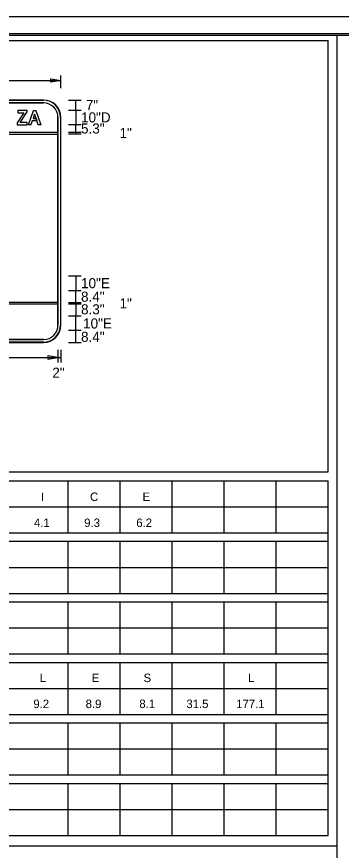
# Model space of a CAD drawing. Extents: x 17890628 to 17890817, y 17897493 to 17897992.
# Drawn here: x 17890717.8 to 17890736.57, y 17897548.59 to 17897596.75 of the extents above; entities that cross this region are included whole.
import ezdxf

# ---------------------------------------------------------------- set-up
doc = ezdxf.new("R2010")
doc.units = 0
for name, color, linetype in [('GSBWFill', 7, 'Continuous'), ('GSColorFill', 7, 'Continuous'), ('GSDims', 7, 'Continuous'), ('GSOutline', 7, 'Continuous'), ('GSSign', 7, 'Continuous'), ('PlotBorder_dp', 7, 'Continuous'), ('SheetBorder_dp', 7, 'Continuous'), ('SheetLinesMisc2_dp', 7, 'Continuous')]:
    doc.layers.add(name, color=color, linetype=linetype)

msp = doc.modelspace()

# ---------------------------------------------------------------- linework, layer by layer
at = {"layer": 'GSBWFill'}
for p, q in [((17890719.353, 17897591.936), (17890701.353, 17897591.936)), ((17890701.353, 17897591.769), (17890719.353, 17897591.769)), ((17890720.187, 17897590.936), (17890720.187, 17897578.936)), ((17890720.353, 17897578.936), (17890720.353, 17897590.936)), ((17890720.187, 17897590.054), (17890700.52, 17897590.054)), ((17890700.52, 17897589.97), (17890720.187, 17897589.97)), ((17890720.187, 17897589.97), (17890720.187, 17897590.054)), ((17890720.187, 17897580.24), (17890700.52, 17897580.24)), ((17890700.52, 17897580.156), (17890720.187, 17897580.156)), ((17890720.187, 17897580.156), (17890720.187, 17897580.24)), ((17890719.353, 17897578.102), (17890701.355, 17897578.102)), ((17890701.355, 17897577.936), (17890719.353, 17897577.936))]:
    msp.add_line(p, q, dxfattribs=at)
for points in [[(17890718.211, 17897591.199), (17890717.837, 17897590.611), (17890717.837, 17897590.499), (17890718.403, 17897590.499), (17890718.403, 17897590.632), (17890718.008, 17897590.632), (17890718.403, 17897591.253), (17890718.403, 17897591.332), (17890717.87, 17897591.332), (17890717.87, 17897591.199)], [(17890718.48, 17897590.499), (17890718.763, 17897591.332), (17890718.905, 17897591.332), (17890719.188, 17897590.499), (17890719.048, 17897590.499), (17890718.834, 17897591.126), (17890718.744, 17897590.861), (17890718.924, 17897590.861), (17890718.97, 17897590.728), (17890718.699, 17897590.728), (17890718.621, 17897590.499)]]:
    msp.add_lwpolyline(points, close=True, dxfattribs=at)
for centre, radius, start, end in [((17890719.353, 17897590.936), 1, 0, 90), ((17890719.353, 17897590.936), 0.833, 0, 90), ((17890719.353, 17897578.936), 1, 270, 0), ((17890719.353, 17897578.936), 0.833, 270, 0)]:
    msp.add_arc(centre, radius, start, end, dxfattribs=at)
at = {"layer": 'GSColorFill'}
for p, q in [((17890719.353, 17897591.936), (17890701.353, 17897591.936)), ((17890719.353, 17897591.936), (17890701.353, 17897591.936)), ((17890719.353, 17897591.936), (17890701.353, 17897591.936)), ((17890701.353, 17897591.919), (17890719.353, 17897591.919)), ((17890701.353, 17897591.769), (17890719.353, 17897591.769)), ((17890720.187, 17897590.936), (17890720.187, 17897578.936)), ((17890720.337, 17897590.936), (17890720.337, 17897578.936)), ((17890720.353, 17897578.936), (17890720.353, 17897590.936)), ((17890720.353, 17897578.936), (17890720.353, 17897590.936)), ((17890720.353, 17897578.936), (17890720.353, 17897590.936)), ((17890720.187, 17897590.054), (17890700.52, 17897590.054)), ((17890700.52, 17897589.97), (17890720.187, 17897589.97)), ((17890720.187, 17897589.97), (17890720.187, 17897590.054)), ((17890720.187, 17897580.24), (17890700.52, 17897580.24)), ((17890700.52, 17897580.156), (17890720.187, 17897580.156)), ((17890720.187, 17897580.156), (17890720.187, 17897580.24)), ((17890719.353, 17897578.102), (17890701.355, 17897578.102)), ((17890701.353, 17897577.936), (17890719.353, 17897577.936)), ((17890719.353, 17897577.952), (17890701.354, 17897577.952)), ((17890701.354, 17897577.936), (17890719.353, 17897577.936)), ((17890701.355, 17897577.936), (17890719.353, 17897577.936))]:
    msp.add_line(p, q, dxfattribs=at)
for points in [[(17890718.211, 17897591.199), (17890717.837, 17897590.611), (17890717.837, 17897590.499), (17890718.403, 17897590.499), (17890718.403, 17897590.632), (17890718.008, 17897590.632), (17890718.403, 17897591.253), (17890718.403, 17897591.332), (17890717.87, 17897591.332), (17890717.87, 17897591.199)], [(17890718.48, 17897590.499), (17890718.763, 17897591.332), (17890718.905, 17897591.332), (17890719.188, 17897590.499), (17890719.048, 17897590.499), (17890718.834, 17897591.126), (17890718.744, 17897590.861), (17890718.924, 17897590.861), (17890718.97, 17897590.728), (17890718.699, 17897590.728), (17890718.621, 17897590.499)]]:
    msp.add_lwpolyline(points, close=True, dxfattribs=at)
for centre, radius, start, end in [((17890719.353, 17897590.936), 1, 0, 90), ((17890719.353, 17897590.936), 1, 0, 90), ((17890719.353, 17897590.936), 1, 0, 90), ((17890719.353, 17897590.936), 0.983, 0, 90), ((17890719.353, 17897590.936), 0.833, 0, 90), ((17890719.353, 17897578.936), 1, 270, 0), ((17890719.353, 17897578.936), 1, 270, 0), ((17890719.353, 17897578.936), 0.833, 270, 0), ((17890719.353, 17897578.936), 1, 270, 0), ((17890719.353, 17897578.936), 0.983, 270, 0)]:
    msp.add_arc(centre, radius, start, end, dxfattribs=at)
at = {"layer": 'GSDims'}
for p, q in [((17890700.353, 17897593.061), (17890720.353, 17897593.061)), ((17890720.353, 17897592.623), (17890720.353, 17897593.353)), ((17890720.791, 17897591.936), (17890721.52, 17897591.936)), ((17890721.228, 17897591.349), (17890721.228, 17897591.936)), ((17890720.791, 17897591.349), (17890721.52, 17897591.349)), ((17890720.791, 17897591.349), (17890721.52, 17897591.349)), ((17890721.228, 17897591.349), (17890721.228, 17897590.516)), ((17890720.791, 17897590.516), (17890721.52, 17897590.516)), ((17890720.791, 17897590.516), (17890721.52, 17897590.516)), ((17890721.228, 17897590.07), (17890721.228, 17897590.516)), ((17890720.791, 17897590.07), (17890721.52, 17897590.07)), ((17890720.791, 17897590.07), (17890721.52, 17897590.07)), ((17890720.791, 17897589.987), (17890721.52, 17897589.987)), ((17890720.791, 17897589.987), (17890721.52, 17897589.987)), ((17890721.228, 17897590.07), (17890721.228, 17897589.987)), ((17890720.791, 17897581.773), (17890721.52, 17897581.773)), ((17890720.791, 17897581.773), (17890721.52, 17897581.773)), ((17890721.228, 17897581.773), (17890721.228, 17897580.939)), ((17890720.791, 17897580.939), (17890721.52, 17897580.939)), ((17890720.791, 17897580.939), (17890721.52, 17897580.939)), ((17890721.228, 17897580.239), (17890721.228, 17897580.939)), ((17890720.791, 17897580.239), (17890721.52, 17897580.239)), ((17890720.791, 17897580.239), (17890721.52, 17897580.239)), ((17890720.791, 17897580.156), (17890721.52, 17897580.156)), ((17890720.791, 17897580.156), (17890721.52, 17897580.156)), ((17890721.228, 17897580.156), (17890721.228, 17897580.239)), ((17890721.228, 17897580.156), (17890721.228, 17897579.468)), ((17890720.791, 17897579.468), (17890721.52, 17897579.468)), ((17890721.228, 17897578.635), (17890721.228, 17897579.468)), ((17890720.791, 17897578.635), (17890721.52, 17897578.635)), ((17890721.228, 17897577.936), (17890721.228, 17897578.635)), ((17890720.791, 17897577.936), (17890721.52, 17897577.936)), ((17890720.187, 17897577.498), (17890720.187, 17897576.769)), ((17890720.187, 17897577.498), (17890720.187, 17897576.769)), ((17890720.354, 17897577.498), (17890720.354, 17897576.769)), ((17890700.52, 17897577.061), (17890720.187, 17897577.061)), ((17890720.187, 17897577.061), (17890720.354, 17897577.061))]:
    msp.add_line(p, q, dxfattribs=at)
for points in [[(17890720.353, 17897593.061), (17890719.77, 17897592.964), (17890719.77, 17897593.158)], [(17890720.187, 17897577.061), (17890719.604, 17897577.158), (17890719.604, 17897576.964)]]:
    msp.add_lwpolyline(points, close=True, dxfattribs=at)
at = {"layer": 'GSOutline'}
for p, q in [((17890719.353, 17897591.936), (17890701.353, 17897591.936)), ((17890719.353, 17897591.769), (17890701.353, 17897591.769)), ((17890720.187, 17897578.936), (17890720.187, 17897590.936)), ((17890720.353, 17897578.936), (17890720.353, 17897590.936)), ((17890720.187, 17897590.054), (17890700.52, 17897590.054)), ((17890700.52, 17897589.97), (17890720.187, 17897589.97)), ((17890720.187, 17897589.97), (17890720.187, 17897590.054)), ((17890720.187, 17897580.24), (17890700.52, 17897580.24)), ((17890700.52, 17897580.156), (17890720.187, 17897580.156)), ((17890720.187, 17897580.156), (17890720.187, 17897580.24)), ((17890701.353, 17897578.102), (17890719.353, 17897578.102)), ((17890701.353, 17897577.936), (17890719.353, 17897577.936))]:
    msp.add_line(p, q, dxfattribs=at)
for points in [[(17890718.211, 17897591.199), (17890717.837, 17897590.611), (17890717.837, 17897590.499), (17890718.403, 17897590.499), (17890718.403, 17897590.632), (17890718.008, 17897590.632), (17890718.403, 17897591.253), (17890718.403, 17897591.332), (17890717.87, 17897591.332), (17890717.87, 17897591.199)], [(17890718.699, 17897590.728), (17890718.621, 17897590.499), (17890718.48, 17897590.499), (17890718.763, 17897591.332), (17890718.905, 17897591.332), (17890719.188, 17897590.499), (17890719.048, 17897590.499), (17890718.97, 17897590.728)], [(17890718.744, 17897590.861), (17890718.924, 17897590.861), (17890718.834, 17897591.126)]]:
    msp.add_lwpolyline(points, close=True, dxfattribs=at)
for centre, radius, start, end in [((17890719.353, 17897590.936), 1, 0, 90), ((17890719.353, 17897590.936), 0.833, 0, 90), ((17890719.353, 17897578.936), 1, 270, 0), ((17890719.353, 17897578.936), 0.833, 270, 0)]:
    msp.add_arc(centre, radius, start, end, dxfattribs=at)
at = {"layer": 'PlotBorder_dp'}
msp.add_lwpolyline([(17890655.57, 17897492.839), (17890817.319, 17897492.839), (17890817.319, 17897596.75), (17890655.57, 17897596.75)], close=True, dxfattribs=at)
at = {"layer": 'SheetBorder_dp'}
msp.add_line((17890660.962, 17897595.77), (17890811.928, 17897595.77), dxfattribs=at)
at = {"layer": 'SheetLinesMisc2_dp'}
for p, q in [((17890661.083, 17897595.691), (17890811.539, 17897595.691)), ((17890736.311, 17897595.691), (17890736.311, 17897502.033)), ((17890684.628, 17897595.379), (17890735.8, 17897595.379)), ((17890735.8, 17897570.453), (17890735.8, 17897595.379)), ((17890684.628, 17897570.453), (17890735.8, 17897570.453)), ((17890661.804, 17897569.94), (17890735.8, 17897569.94)), ((17890720.749, 17897569.94), (17890720.749, 17897566.933)), ((17890723.759, 17897569.94), (17890723.759, 17897566.933)), ((17890726.769, 17897569.94), (17890726.769, 17897566.933)), ((17890729.779, 17897569.94), (17890729.779, 17897566.933)), ((17890732.79, 17897569.94), (17890732.79, 17897566.933)), ((17890735.8, 17897549.452), (17890735.8, 17897569.94)), ((17890661.804, 17897568.437), (17890735.8, 17897568.437)), ((17890661.804, 17897566.933), (17890735.8, 17897566.933)), ((17890661.804, 17897566.443), (17890735.8, 17897566.443)), ((17890720.749, 17897566.443), (17890720.749, 17897563.437)), ((17890723.759, 17897566.443), (17890723.759, 17897563.437)), ((17890726.769, 17897566.443), (17890726.769, 17897563.437)), ((17890729.779, 17897566.443), (17890729.779, 17897563.437)), ((17890732.79, 17897566.443), (17890732.79, 17897563.437)), ((17890661.804, 17897564.94), (17890735.8, 17897564.94)), ((17890661.804, 17897563.437), (17890735.8, 17897563.437)), ((17890661.804, 17897562.947), (17890735.8, 17897562.947)), ((17890720.749, 17897562.947), (17890720.749, 17897559.941)), ((17890723.759, 17897562.947), (17890723.759, 17897559.941)), ((17890726.769, 17897562.947), (17890726.769, 17897559.941)), ((17890729.779, 17897562.947), (17890729.779, 17897559.941)), ((17890732.79, 17897562.947), (17890732.79, 17897559.941)), ((17890661.804, 17897561.444), (17890735.8, 17897561.444)), ((17890661.804, 17897559.941), (17890735.8, 17897559.941)), ((17890661.804, 17897559.451), (17890735.8, 17897559.451)), ((17890720.749, 17897559.451), (17890720.749, 17897556.444)), ((17890723.759, 17897559.451), (17890723.759, 17897556.444)), ((17890726.769, 17897559.451), (17890726.769, 17897556.444)), ((17890729.779, 17897559.451), (17890729.779, 17897556.444)), ((17890732.79, 17897559.451), (17890732.79, 17897556.444)), ((17890661.804, 17897557.947), (17890735.8, 17897557.947)), ((17890661.804, 17897556.444), (17890735.8, 17897556.444)), ((17890661.804, 17897555.954), (17890735.8, 17897555.954)), ((17890720.749, 17897555.954), (17890720.749, 17897552.948)), ((17890723.759, 17897555.954), (17890723.759, 17897552.948)), ((17890726.769, 17897555.954), (17890726.769, 17897552.948)), ((17890729.779, 17897555.954), (17890729.779, 17897552.948)), ((17890732.79, 17897555.954), (17890732.79, 17897552.948)), ((17890661.804, 17897554.451), (17890735.8, 17897554.451)), ((17890661.804, 17897552.948), (17890735.8, 17897552.948)), ((17890661.804, 17897552.458), (17890735.8, 17897552.458)), ((17890720.749, 17897552.458), (17890720.749, 17897549.452)), ((17890723.759, 17897552.458), (17890723.759, 17897549.452)), ((17890726.769, 17897552.458), (17890726.769, 17897549.452)), ((17890729.779, 17897552.458), (17890729.779, 17897549.452)), ((17890732.79, 17897552.458), (17890732.79, 17897549.452)), ((17890661.804, 17897550.955), (17890735.8, 17897550.955)), ((17890661.804, 17897549.452), (17890735.8, 17897549.452)), ((17890661.083, 17897548.861), (17890736.311, 17897548.861))]:
    msp.add_line(p, q, dxfattribs=at)

# ---------------------------------------------------------------- texts
at = {"layer": 'GSDims'}
for s, p in [('7"', (17890721.797, 17897591.351)), ('10"D', (17890721.52, 17897590.641)), ('5.3"', (17890721.52, 17897590.001)), ('1"', (17890723.746, 17897589.737)), ('10"E', (17890721.52, 17897581.064)), ('8.4"', (17890721.52, 17897580.284)), ('1"', (17890723.746, 17897579.896)), ('8.3"', (17890721.52, 17897579.554)), ('10"E', (17890721.639, 17897578.739)), ('8.4"', (17890721.52, 17897577.967)), ('2"', (17890719.861, 17897575.894))]:
    msp.add_text(s, height=0.5833, dxfattribs=at).set_placement(p)
at = {"layer": 'GSSign'}
for s, height, p in [('I', 0.49, (17890719.206, 17897568.773)), ('C', 0.49, (17890722.041, 17897568.773)), ('E', 0.49, (17890725.075, 17897568.773)), ('4.1', 0.4902, (17890718.797, 17897567.27)), ('9.3', 0.4902, (17890721.703, 17897567.27)), ('6.2', 0.4902, (17890724.713, 17897567.27)), ('L', 0.49, (17890719.138, 17897558.313)), ('E', 0.49, (17890722.137, 17897558.313)), ('S', 0.49, (17890725.135, 17897558.313)), ('L', 0.49, (17890731.179, 17897558.313)), ('9.2', 0.4902, (17890718.764, 17897556.81)), ('8.9', 0.4902, (17890721.786, 17897556.81)), ('8.1', 0.4902, (17890724.89, 17897556.81)), ('31.5', 0.4902, (17890727.609, 17897556.81)), ('177.1', 0.4902, (17890730.491, 17897556.81))]:
    msp.add_text(s, height=height, dxfattribs=at).set_placement(p)

doc.saveas('drawing.dxf')
